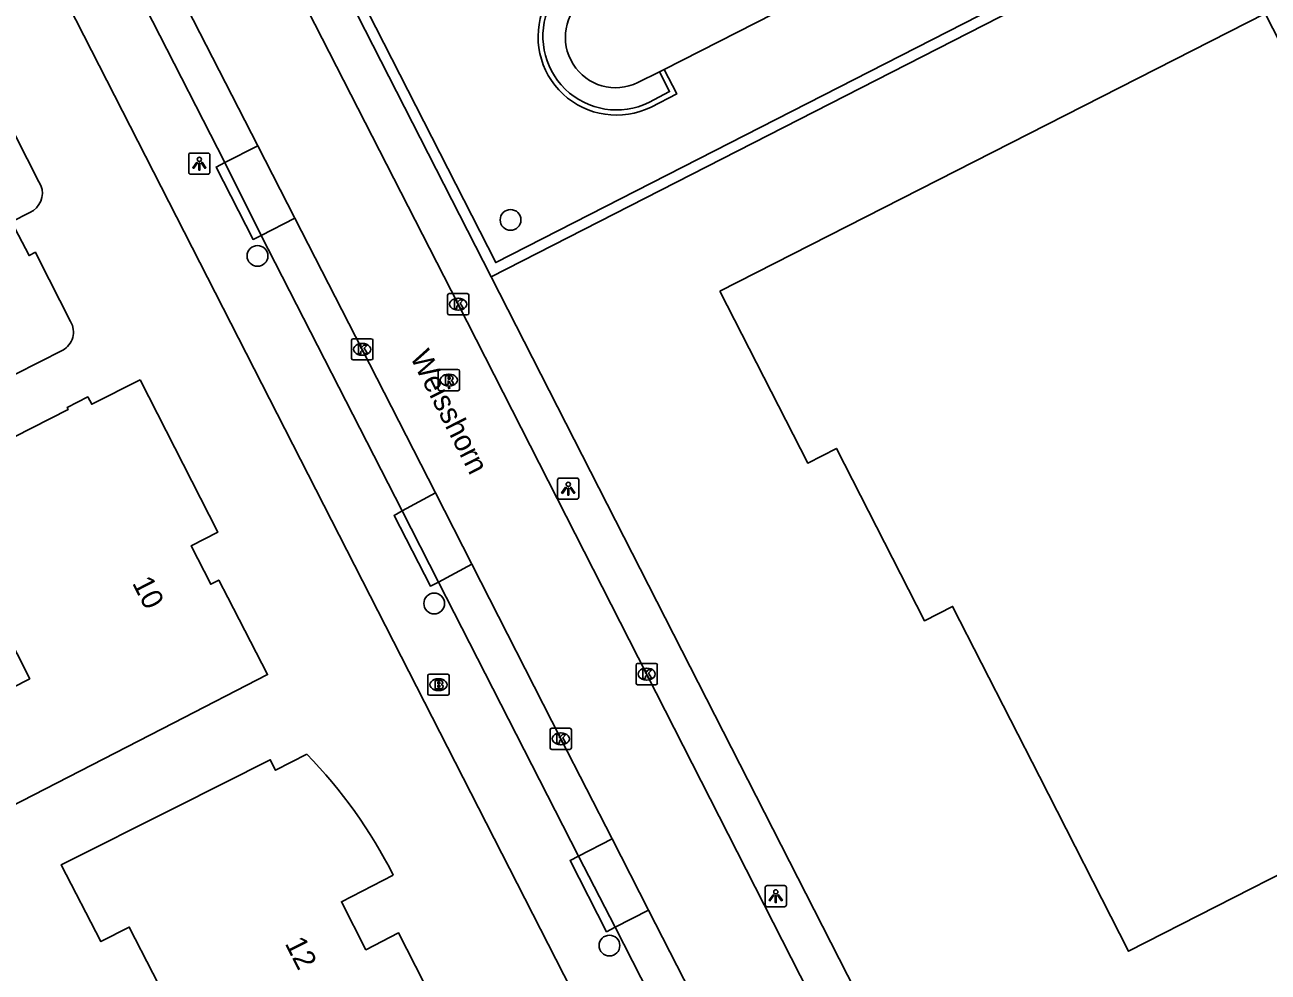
# Model space of a CAD drawing. Extents: x 158838 to 160074, y 386376 to 387776.
# Drawn here: x 159539.8 to 159598.3, y 386802 to 386846.6 of the extents above; entities that cross this region are included whole.
import ezdxf

# ---------------------------------------------------------------- set-up
doc = ezdxf.new("R2010")
doc.units = 0
for name, color, linetype in [('IMGEO_Boom', 7, 'Continuous'), ('IMGEO_Brandkraan', 7, 'Continuous'), ('IMGEO_Haag', 7, 'Continuous'), ('IMGEO_Kolk', 7, 'Continuous'), ('IMGEO_Lichtpunt', 7, 'Continuous'), ('IMGEO_Openbare_ruimte_label', 7, 'Continuous'), ('IMGEO_Pand', 7, 'Continuous'), ('IMGEO_Pand_nummerreeks', 7, 'Continuous'), ('IMGEO_Pand_vergunning_verleend', 7, 'Continuous'), ('IMGEO_Parkeervlak_open', 7, 'Continuous'), ('IMGEO_Rioolput', 7, 'Continuous'), ('IMGEO_Voetpad_open', 7, 'Continuous')]:
    doc.layers.add(name, color=color, linetype=linetype)

msp = doc.modelspace()

# ---------------------------------------------------------------- linework, layer by layer
at = {"layer": 'IMGEO_Boom'}
for centre in [(159562.671, 386837.44), (159550.762, 386835.746), (159559.077, 386819.38), (159567.324, 386803.273)]:
    msp.add_circle(centre, 0.489, dxfattribs=at)
at = {"layer": 'IMGEO_Brandkraan'}
for p, q in [((159558.778, 386815.131), (159558.778, 386815.983)), ((159558.853, 386816.057), (159559.705, 386816.057)), ((159559.266, 386815.837), (159559.291, 386815.837)), ((159559.779, 386815.983), (159559.779, 386815.131)), ((159559.705, 386815.057), (159558.853, 386815.057)), ((159559.289, 386815.277), (159559.264, 386815.277))]:
    msp.add_line(p, q, dxfattribs=at)
for points in [[(159558.778, 386815.131), (159558.778, 386815.983)], [(159558.853, 386816.057), (159559.705, 386816.057)], [(159559.126, 386815.757), (159559.126, 386815.357), (159559.339, 386815.357)], [(159559.357, 386815.757), (159559.126, 386815.757)], [(159559.305, 386815.676), (159559.251, 386815.676), (159559.251, 386815.6)], [(159559.251, 386815.6), (159559.304, 386815.6)], [(159559.779, 386815.983), (159559.779, 386815.131)], [(159559.705, 386815.057), (159558.853, 386815.057)], [(159559.313, 386815.524), (159559.251, 386815.524), (159559.251, 386815.443)], [(159559.251, 386815.443), (159559.313, 386815.443)]]:
    msp.add_lwpolyline(points, dxfattribs=at)
for centre, radius, start, end in [((159558.855, 386815.981), 0.0765, 91.55205, 178.44795), ((159558.855, 386815.981), 0.0765, 91.55205, 178.44795), ((159559.306, 386815.638), 0.0379, 267.82845, 90.93552), ((159559.361, 386815.612), 0.145, 59.4692, 91.53667), ((159559.386, 386815.659), 0.0922, 285.51372, 58.15012), ((159559.391, 386815.467), 0.105, 301.31148, 78.98903), ((159559.703, 386815.981), 0.0765, 1.55205, 88.44795), ((159559.703, 386815.981), 0.0765, 1.55205, 88.44795), ((159558.855, 386815.133), 0.0765, 181.55205, 268.44795), ((159558.855, 386815.133), 0.0765, 181.55205, 268.44795), ((159559.314, 386815.483), 0.0404, 269.87594, 90.50774), ((159559.345, 386815.608), 0.251, 268.66757, 293.53466), ((159559.703, 386815.133), 0.0765, 271.55205, 358.44795), ((159559.703, 386815.133), 0.0765, 271.55205, 358.44795)]:
    msp.add_arc(centre, radius, start, end, dxfattribs=at)
for centre, major_axis, ratio, start_param, end_param in [((159559.265, 386815.557), (-0.387, 0.002), 0.722429, 4.712389, 7.853982), ((159559.29, 386815.557), (-0.39, 0.002), 0.717154, 1.570796, 4.712389)]:
    msp.add_ellipse(centre, major_axis=major_axis, ratio=ratio, start_param=start_param, end_param=end_param, dxfattribs=at)
at = {"layer": 'IMGEO_Haag'}
for points in [[(159597.279, 386891.352), (159612.561, 386861.297), (159561.976, 386835.435), (159552.94, 386853.159)], [(159561.758, 386834.762), (159613.233, 386861.079)]]:
    msp.add_lwpolyline(points, dxfattribs=at)
at = {"layer": 'IMGEO_Kolk'}
for p, q in [((159559.705, 386833.047), (159559.705, 386833.899)), ((159559.78, 386833.973), (159560.632, 386833.973)), ((159560.193, 386833.753), (159560.218, 386833.753)), ((159560.706, 386833.899), (159560.706, 386833.047)), ((159560.216, 386833.193), (159560.191, 386833.193)), ((159560.632, 386832.973), (159559.78, 386832.973)), ((159555.187, 386830.921), (159555.187, 386831.773)), ((159555.262, 386831.847), (159556.114, 386831.847)), ((159555.675, 386831.627), (159555.7, 386831.627)), ((159556.188, 386831.773), (159556.188, 386830.921)), ((159556.114, 386830.847), (159555.262, 386830.847)), ((159555.698, 386831.067), (159555.673, 386831.067)), ((159568.577, 386815.63), (159568.577, 386816.482)), ((159568.652, 386816.556), (159569.504, 386816.556)), ((159569.065, 386816.336), (159569.09, 386816.336)), ((159569.578, 386816.482), (159569.578, 386815.63)), ((159569.504, 386815.556), (159568.652, 386815.556)), ((159569.088, 386815.776), (159569.063, 386815.776)), ((159564.535, 386812.582), (159564.535, 386813.434)), ((159564.61, 386813.508), (159565.462, 386813.508)), ((159565.023, 386813.288), (159565.048, 386813.288)), ((159565.536, 386813.434), (159565.536, 386812.582)), ((159565.046, 386812.728), (159565.021, 386812.728)), ((159565.462, 386812.508), (159564.61, 386812.508))]:
    msp.add_line(p, q, dxfattribs=at)
for points in [[(159559.705, 386833.047), (159559.705, 386833.899)], [(159559.78, 386833.973), (159560.632, 386833.973)], [(159560.706, 386833.899), (159560.706, 386833.047)], [(159560.026, 386833.673), (159560.149, 386833.673), (159560.149, 386833.522), (159560.279, 386833.673), (159560.443, 386833.673), (159560.297, 386833.522), (159560.45, 386833.273), (159560.298, 386833.273), (159560.213, 386833.437), (159560.149, 386833.37), (159560.149, 386833.273), (159560.026, 386833.273), (159560.026, 386833.673)], [(159560.632, 386832.973), (159559.78, 386832.973)], [(159555.187, 386830.921), (159555.187, 386831.773)], [(159555.262, 386831.847), (159556.114, 386831.847)], [(159555.508, 386831.547), (159555.631, 386831.547), (159555.631, 386831.396), (159555.761, 386831.547), (159555.925, 386831.547), (159555.779, 386831.396), (159555.932, 386831.147), (159555.78, 386831.147), (159555.695, 386831.311), (159555.631, 386831.244), (159555.631, 386831.147), (159555.508, 386831.147), (159555.508, 386831.547)], [(159556.188, 386831.773), (159556.188, 386830.921)], [(159556.114, 386830.847), (159555.262, 386830.847)], [(159568.577, 386815.63), (159568.577, 386816.482)], [(159568.652, 386816.556), (159569.504, 386816.556)], [(159568.898, 386816.256), (159569.021, 386816.256), (159569.021, 386816.105), (159569.151, 386816.256), (159569.315, 386816.256), (159569.169, 386816.105), (159569.322, 386815.856), (159569.17, 386815.856), (159569.085, 386816.02), (159569.021, 386815.953), (159569.021, 386815.856), (159568.898, 386815.856), (159568.898, 386816.256)], [(159569.578, 386816.482), (159569.578, 386815.63)], [(159569.504, 386815.556), (159568.652, 386815.556)], [(159564.535, 386812.582), (159564.535, 386813.434)], [(159564.61, 386813.508), (159565.462, 386813.508)], [(159565.536, 386813.434), (159565.536, 386812.582)], [(159564.856, 386813.208), (159564.979, 386813.208), (159564.979, 386813.057), (159565.109, 386813.208), (159565.273, 386813.208), (159565.127, 386813.057), (159565.28, 386812.808), (159565.128, 386812.808), (159565.043, 386812.972), (159564.979, 386812.905), (159564.979, 386812.808), (159564.856, 386812.808), (159564.856, 386813.208)], [(159565.462, 386812.508), (159564.61, 386812.508)]]:
    msp.add_lwpolyline(points, dxfattribs=at)
for centre, start, end in [((159559.782, 386833.897), 91.55205, 178.44795), ((159559.782, 386833.897), 91.55205, 178.44795), ((159560.63, 386833.897), 1.55205, 88.44795), ((159560.63, 386833.897), 1.55205, 88.44795), ((159559.782, 386833.049), 181.55205, 268.44795), ((159559.782, 386833.049), 181.55205, 268.44795), ((159560.63, 386833.049), 271.55205, 358.44795), ((159560.63, 386833.049), 271.55205, 358.44795), ((159555.264, 386831.771), 91.55205, 178.44795), ((159555.264, 386831.771), 91.55205, 178.44795), ((159556.112, 386831.771), 1.55205, 88.44795), ((159556.112, 386831.771), 1.55205, 88.44795), ((159555.264, 386830.923), 181.55205, 268.44795), ((159555.264, 386830.923), 181.55205, 268.44795), ((159556.112, 386830.923), 271.55205, 358.44795), ((159556.112, 386830.923), 271.55205, 358.44795), ((159568.654, 386816.48), 91.55205, 178.44795), ((159568.654, 386816.48), 91.55205, 178.44795), ((159569.502, 386816.48), 1.55205, 88.44795), ((159569.502, 386816.48), 1.55205, 88.44795), ((159568.654, 386815.632), 181.55205, 268.44795), ((159568.654, 386815.632), 181.55205, 268.44795), ((159569.502, 386815.632), 271.55205, 358.44795), ((159569.502, 386815.632), 271.55205, 358.44795), ((159564.612, 386813.432), 91.55205, 178.44795), ((159564.612, 386813.432), 91.55205, 178.44795), ((159565.46, 386813.432), 1.55205, 88.44795), ((159565.46, 386813.432), 1.55205, 88.44795), ((159564.612, 386812.584), 181.55205, 268.44795), ((159564.612, 386812.584), 181.55205, 268.44795), ((159565.46, 386812.584), 271.55205, 358.44795), ((159565.46, 386812.584), 271.55205, 358.44795)]:
    msp.add_arc(centre, 0.0765, start, end, dxfattribs=at)
for centre, major_axis, ratio, start_param, end_param in [((159560.192, 386833.473), (-0.387, 0.002), 0.722429, 4.712389, 7.853982), ((159560.217, 386833.473), (-0.39, 0.002), 0.717154, 1.570796, 4.712389), ((159555.674, 386831.347), (-0.387, 0.002), 0.722429, 4.712389, 7.853982), ((159555.699, 386831.347), (-0.39, 0.002), 0.717154, 1.570796, 4.712389), ((159569.064, 386816.056), (-0.387, 0.002), 0.722429, 4.712389, 7.853982), ((159569.089, 386816.056), (-0.39, 0.002), 0.717154, 1.570796, 4.712389), ((159565.022, 386813.008), (-0.387, 0.002), 0.722429, 4.712389, 7.853982), ((159565.047, 386813.008), (-0.39, 0.002), 0.717154, 1.570796, 4.712389)]:
    msp.add_ellipse(centre, major_axis=major_axis, ratio=ratio, start_param=start_param, end_param=end_param, dxfattribs=at)
at = {"layer": 'IMGEO_Lichtpunt'}
for p, q in [((159547.526, 386840.495), (159547.526, 386839.688)), ((159547.526, 386840.495), (159547.526, 386839.688)), ((159548.428, 386840.59), (159547.62, 386840.59)), ((159548.428, 386840.59), (159547.62, 386840.59)), ((159548.522, 386839.688), (159548.522, 386840.495)), ((159548.522, 386839.688), (159548.522, 386840.495)), ((159547.62, 386839.594), (159548.428, 386839.594)), ((159547.62, 386839.594), (159548.428, 386839.594)), ((159564.886, 386825.192), (159564.886, 386824.385)), ((159564.886, 386825.192), (159564.886, 386824.385)), ((159565.788, 386825.287), (159564.98, 386825.287)), ((159565.788, 386825.287), (159564.98, 386825.287)), ((159565.882, 386824.385), (159565.882, 386825.192)), ((159565.882, 386824.385), (159565.882, 386825.192)), ((159564.98, 386824.291), (159565.788, 386824.291)), ((159564.98, 386824.291), (159565.788, 386824.291)), ((159574.654, 386806.003), (159574.654, 386805.196)), ((159574.654, 386806.003), (159574.654, 386805.196)), ((159575.556, 386806.098), (159574.748, 386806.098)), ((159575.556, 386806.098), (159574.748, 386806.098)), ((159575.65, 386805.196), (159575.65, 386806.003)), ((159575.65, 386805.196), (159575.65, 386806.003)), ((159574.748, 386805.102), (159575.556, 386805.102)), ((159574.748, 386805.102), (159575.556, 386805.102))]:
    msp.add_line(p, q, dxfattribs=at)
for points in [[(159547.9, 386840.159), (159547.939, 386840.131), (159547.751, 386839.869), (159547.713, 386839.896), (159547.9, 386840.159)], [(159548.112, 386840.131), (159548.15, 386840.158), (159548.337, 386839.896), (159548.298, 386839.868), (159548.112, 386840.131)], [(159548.002, 386840.111), (159548.049, 386840.111), (159548.049, 386839.789), (159548.002, 386839.789), (159548.002, 386840.111)], [(159565.26, 386824.856), (159565.299, 386824.828), (159565.111, 386824.566), (159565.073, 386824.593), (159565.26, 386824.856)], [(159565.362, 386824.808), (159565.409, 386824.808), (159565.409, 386824.486), (159565.362, 386824.486), (159565.362, 386824.808)], [(159565.472, 386824.828), (159565.51, 386824.855), (159565.697, 386824.593), (159565.658, 386824.565), (159565.472, 386824.828)], [(159575.028, 386805.667), (159575.067, 386805.639), (159574.879, 386805.377), (159574.841, 386805.404), (159575.028, 386805.667)], [(159575.13, 386805.619), (159575.177, 386805.619), (159575.177, 386805.297), (159575.13, 386805.297), (159575.13, 386805.619)], [(159575.24, 386805.639), (159575.278, 386805.666), (159575.465, 386805.404), (159575.426, 386805.376), (159575.24, 386805.639)]]:
    msp.add_lwpolyline(points, dxfattribs=at)
for centre in [(159548.025, 386840.293), (159565.385, 386824.99), (159575.153, 386805.801)]:
    msp.add_circle(centre, 0.0994, dxfattribs=at)
for centre, start, end in [((159547.62, 386840.495), 90, 180), ((159547.62, 386840.495), 90, 180), ((159548.428, 386840.495), 0, 90), ((159548.428, 386840.495), 0, 90), ((159547.62, 386839.688), 180, 270), ((159547.62, 386839.688), 180, 270), ((159548.428, 386839.688), 270, 0), ((159548.428, 386839.688), 270, 360), ((159564.98, 386825.192), 90, 180), ((159564.98, 386825.192), 90, 180), ((159565.788, 386825.192), 0, 90), ((159565.788, 386825.192), 0, 90), ((159564.98, 386824.385), 180, 270), ((159564.98, 386824.385), 180, 270), ((159565.788, 386824.385), 270, 0), ((159565.788, 386824.385), 270, 360), ((159574.748, 386806.003), 90, 180), ((159574.748, 386806.003), 90, 180), ((159575.556, 386806.003), 0, 90), ((159575.556, 386806.003), 0, 90), ((159574.748, 386805.196), 180, 270), ((159574.748, 386805.196), 180, 270), ((159575.556, 386805.196), 270, 0), ((159575.556, 386805.196), 270, 360)]:
    msp.add_arc(centre, 0.0946, start, end, dxfattribs=at)
at = {"layer": 'IMGEO_Pand'}
for points in [[(159569.897, 386844.528), (159593.104, 386856.363), (159590.164, 386862.144), (159588.81, 386861.455), (159586.568, 386865.834), (159588.934, 386867.048), (159585.292, 386874.15), (159582.943, 386872.945), (159580.713, 386877.335), (159582.066, 386878.026), (159579.12, 386883.794), (159564.646, 386876.407)], [(159540.568, 386839.059), (159540.475, 386839.239), (159537.731, 386844.612), (159533.278, 386842.338), (159530.784, 386841.065), (159530.331, 386841.96), (159525.322, 386839.422), (159527.012, 386836.085), (159526.71, 386835.93), (159527.557, 386834.274), (159527.86, 386834.429), (159531.98, 386826.383), (159537.134, 386829.042), (159541.593, 386831.304)], [(159568.662, 386843.906), (159569.674, 386844.414)], [(159569.674, 386844.414), (159569.897, 386844.528)], [(159541.968, 386832.656), (159540.461, 386835.626), (159540.313, 386835.918), (159540.01, 386835.765), (159539.187, 386837.347), (159540.055, 386837.792)], [(159545.237, 386829.917), (159542.961, 386828.765), (159542.776, 386829.107), (159541.808, 386828.615), (159541.857, 386828.517), (159534.233, 386824.63), (159535.174, 386822.784), (159534.586, 386822.484), (159536.591, 386818.552), (159538.231, 386819.389), (159540.041, 386815.84), (159535.208, 386813.376), (159537.482, 386808.957), (159546.791, 386813.743), (159551.236, 386816.033), (159549.365, 386819.664), (159548.942, 386820.485), (159548.558, 386820.29), (159547.633, 386822.093), (159548.89, 386822.732), (159545.237, 386829.917)], [(159553.085, 386812.287), (159551.61, 386811.532), (159551.364, 386812.022), (159546.896, 386809.779), (159541.524, 386807.082), (159543.393, 386803.458), (159544.723, 386804.144), (159546.956, 386799.815), (159543.751, 386798.162), (159546.274, 386793.271), (159554.94, 386797.687), (159559.393, 386799.961), (159557.392, 386803.88), (159555.863, 386803.079), (159554.714, 386805.335), (159557.152, 386806.583)]]:
    msp.add_lwpolyline(points, dxfattribs=at)
for centre, radius, start, end in [((159567.62, 386846.036), 2.371, 128.07354, 296.05827), ((159539.643, 386838.696), 0.993, 294.48053, 21.43406), ((159541.117, 386832.164), 0.983, 298.97986, 30.01564), ((159536.72, 386796.317), 22.866, 26.67783, 44.30055)]:
    msp.add_arc(centre, radius, start, end, dxfattribs=at)
at = {"layer": 'IMGEO_Pand_vergunning_verleend'}
msp.add_lwpolyline([(159572.527, 386834.081), (159598.185, 386847.168), (159602.213, 386839.272), (159603.957, 386840.161), (159608.271, 386831.704), (159604.3, 386829.679), (159608.255, 386821.924), (159612.25, 386823.962), (159616.502, 386815.625), (159591.756, 386803.003), (159587.559, 386811.231), (159583.473, 386819.241), (159582.148, 386818.565), (159578.008, 386826.682), (159576.654, 386825.992), (159572.527, 386834.081)], dxfattribs=at)
at = {"layer": 'IMGEO_Parkeervlak_open'}
for points in [[(159549.217, 386840.137), (159550.778, 386840.934)], [(159552.523, 386837.528), (159550.933, 386836.714)], [(159557.569, 386823.739), (159559.136, 386824.585)], [(159560.845, 386821.233), (159559.274, 386820.378)], [(159565.863, 386807.488), (159567.447, 386808.298)], [(159569.168, 386804.935), (159567.6, 386804.133)]]:
    msp.add_lwpolyline(points, dxfattribs=at)
at = {"layer": 'IMGEO_Rioolput'}
for p, q in [((159559.266, 386829.473), (159559.266, 386830.325)), ((159559.341, 386830.399), (159560.193, 386830.399)), ((159559.754, 386830.179), (159559.779, 386830.179)), ((159560.267, 386830.325), (159560.267, 386829.473)), ((159559.777, 386829.619), (159559.752, 386829.619)), ((159560.193, 386829.399), (159559.341, 386829.399))]:
    msp.add_line(p, q, dxfattribs=at)
for points in [[(159559.266, 386829.473), (159559.266, 386830.325)], [(159559.341, 386830.399), (159560.193, 386830.399)], [(159560.267, 386830.325), (159560.267, 386829.473)], [(159559.855, 386830.097), (159559.603, 386830.099), (159559.603, 386829.699)], [(159559.603, 386829.699), (159559.727, 386829.699), (159559.727, 386829.861), (159559.738, 386829.861)], [(159559.781, 386830.018), (159559.727, 386830.018), (159559.727, 386829.937)], [(159559.727, 386829.937), (159559.779, 386829.937)], [(159559.785, 386829.832), (159559.856, 386829.699), (159559.996, 386829.699), (159559.931, 386829.825)], [(159560.193, 386829.399), (159559.341, 386829.399)]]:
    msp.add_lwpolyline(points, dxfattribs=at)
for centre, radius, start, end in [((159559.343, 386830.323), 0.0765, 91.55205, 178.44795), ((159559.343, 386830.323), 0.0765, 91.55205, 178.44795), ((159560.191, 386830.323), 0.0765, 1.55205, 88.44795), ((159560.191, 386830.323), 0.0765, 1.55205, 88.44795), ((159559.737, 386829.808), 0.0533, 26.02933, 88.69889), ((159559.763, 386830.126), 0.19, 274.7715, 282.96867), ((159559.787, 386829.922), 0.0964, 77.00612, 93.18647), ((159559.801, 386829.979), 0.0378, 276.66336, 79.67722), ((159559.854, 386829.987), 0.109, 350.36119, 89.41601), ((159559.852, 386829.987), 0.112, 277.58423, 350.98172), ((159559.836, 386829.772), 0.108, 29.51342, 73.79051), ((159559.343, 386829.475), 0.0765, 181.55205, 268.44795), ((159559.343, 386829.475), 0.0765, 181.55205, 268.44795), ((159560.191, 386829.475), 0.0765, 271.55205, 358.44795), ((159560.191, 386829.475), 0.0765, 271.55205, 358.44795)]:
    msp.add_arc(centre, radius, start, end, dxfattribs=at)
for centre, major_axis, ratio, start_param, end_param in [((159559.753, 386829.899), (-0.387, 0.002), 0.722429, 4.712389, 7.853982), ((159559.778, 386829.899), (-0.39, 0.002), 0.717154, 1.570796, 4.712389)]:
    msp.add_ellipse(centre, major_axis=major_axis, ratio=ratio, start_param=start_param, end_param=end_param, dxfattribs=at)
at = {"layer": 'IMGEO_Voetpad_open'}
for points in [[(159584.383, 386786.038), (159577.577, 386799.373), (159560.205, 386833.473), (159551.113, 386851.265), (159542.784, 386867.593)], [(159531.993, 386866.849), (159573.913, 386784.786)], [(159544.016, 386854.223), (159546.828, 386848.645), (159550.778, 386840.934)], [(159549.217, 386840.137), (159542.42, 386853.463)], [(159561.758, 386834.762), (159552.494, 386852.932)], [(159569.181, 386842.971), (159570.152, 386843.481), (159569.674, 386844.414)], [(159569.897, 386844.528), (159570.489, 386843.372), (159569.285, 386842.752)], [(159550.778, 386840.934), (159552.523, 386837.528)], [(159550.933, 386836.714), (159550.553, 386836.525), (159548.81, 386839.929), (159549.217, 386840.137)], [(159550.933, 386836.714), (159549.217, 386840.137)], [(159559.136, 386824.585), (159555.689, 386831.347), (159552.523, 386837.528)], [(159557.569, 386823.739), (159550.933, 386836.714)], [(159583.195, 386792.717), (159561.758, 386834.762)], [(159559.136, 386824.585), (159560.845, 386821.233)], [(159559.274, 386820.378), (159558.901, 386820.197), (159557.193, 386823.53), (159557.569, 386823.739)], [(159557.569, 386823.739), (159559.274, 386820.378)], [(159567.447, 386808.298), (159565.037, 386813.009), (159560.845, 386821.233)], [(159565.863, 386807.488), (159559.274, 386820.378)], [(159567.447, 386808.298), (159569.168, 386804.935)], [(159567.6, 386804.133), (159567.19, 386803.92), (159565.475, 386807.279), (159565.863, 386807.488)], [(159565.863, 386807.488), (159567.6, 386804.133)], [(159576.469, 386790.665), (159569.168, 386804.935)], [(159574.878, 386789.851), (159567.6, 386804.133)]]:
    msp.add_lwpolyline(points, dxfattribs=at)
for centre, radius, start, end in [((159567.659, 386846.066), 3.691, 157.8251, 296.13367), ((159567.66, 386846.084), 3.465, 155.60282, 296.03764)]:
    msp.add_arc(centre, radius, start, end, dxfattribs=at)

# ---------------------------------------------------------------- texts
at = {"layer": 'IMGEO_Openbare_ruimte_label'}
msp.add_text('Weisshorn', height=1, rotation=297.00065, dxfattribs=at).set_placement((159557.918, 386831))
at = {"layer": 'IMGEO_Pand_nummerreeks'}
for s, rotation, p in [('10', 297.15936, (159544.843, 386820.346)), ('12', 296.99013, (159552.031, 386803.376))]:
    msp.add_text(s, height=1, rotation=rotation, dxfattribs=at).set_placement(p)

doc.saveas('drawing.dxf')
